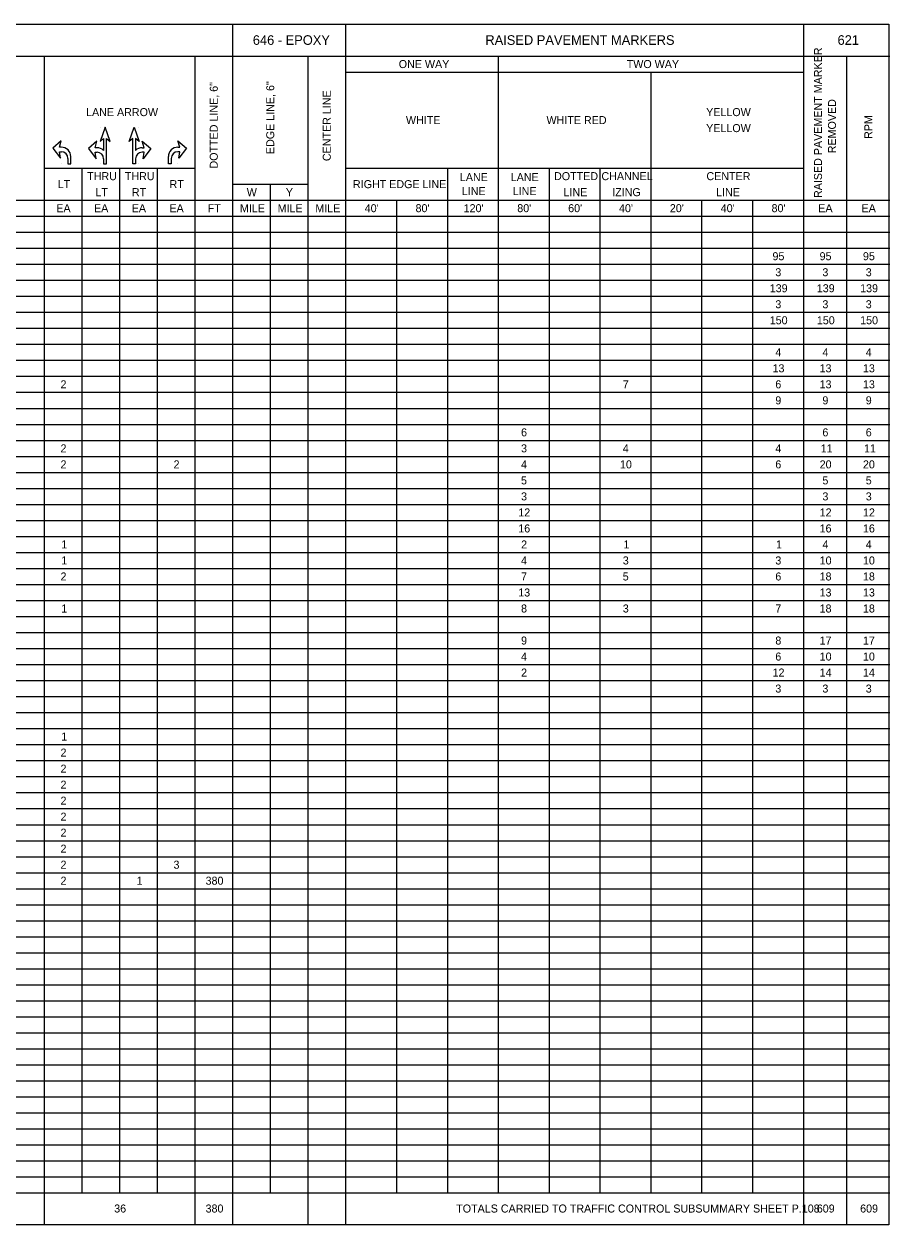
# Model space of a CAD drawing. Extents: x 12522 to 13018, y 1124 to 1902.
# Drawn here: x 12888.52 to 12903.67, y 1804.65 to 1825.65 of the extents above; entities that cross this region are included whole.
import ezdxf

# ---------------------------------------------------------------- set-up
doc = ezdxf.new("R2010")
doc.units = 0
for name, color, linetype in [('MT_X_Cells', 7, 'Continuous'), ('PM_P_Cells', 7, 'Continuous'), ('SC_Scratch1', 7, 'Continuous'), ('SH_Data', 7, 'Continuous'), ('SH_Text', 7, 'Continuous')]:
    doc.layers.add(name, color=color, linetype=linetype)

msp = doc.modelspace()

# ---------------------------------------------------------------- linework, layer by layer
at = {"layer": 'MT_X_Cells'}
for p, q in [((12889.941, 1823.846), (12889.854, 1823.596)), ((12889.854, 1823.596), (12889.916, 1823.646)), ((12889.858, 1823.846), (12889.858, 1823.846)), ((12890.028, 1823.596), (12889.941, 1823.846)), ((12889.966, 1823.208), (12889.966, 1823.646)), ((12889.966, 1823.646), (12890.028, 1823.596)), ((12890.362, 1823.596), (12890.449, 1823.846)), ((12890.424, 1823.646), (12890.362, 1823.596)), ((12890.424, 1823.208), (12890.424, 1823.646)), ((12890.449, 1823.846), (12890.535, 1823.596)), ((12890.535, 1823.596), (12890.474, 1823.646)), ((12890.532, 1823.846), (12890.532, 1823.846)), ((12889.799, 1823.599), (12889.649, 1823.471)), ((12889.649, 1823.471), (12889.783, 1823.295)), ((12889.766, 1823.487), (12889.799, 1823.599)), ((12889.799, 1823.487), (12889.766, 1823.487)), ((12890.624, 1823.487), (12890.59, 1823.599)), ((12890.59, 1823.599), (12890.74, 1823.471)), ((12890.59, 1823.487), (12890.624, 1823.487)), ((12890.74, 1823.471), (12890.607, 1823.295)), ((12889.783, 1823.295), (12889.766, 1823.407)), ((12889.766, 1823.407), (12889.801, 1823.407)), ((12889.916, 1823.292), (12889.916, 1823.208)), ((12890.474, 1823.292), (12890.474, 1823.208)), ((12890.624, 1823.407), (12890.588, 1823.407)), ((12890.607, 1823.295), (12890.624, 1823.407)), ((12889.858, 1823.208), (12889.858, 1823.208)), ((12889.916, 1823.208), (12889.966, 1823.208)), ((12890.474, 1823.208), (12890.424, 1823.208)), ((12890.532, 1823.208), (12890.532, 1823.208))]:
    msp.add_line(p, q, dxfattribs=at)
for points in [[(12889.916, 1823.646), (12889.916, 1823.44)], [(12890.474, 1823.646), (12890.474, 1823.44)]]:
    msp.add_lwpolyline(points, dxfattribs=at)
for centre, radius, start, end in [((12889.802, 1823.323), 0.164, 45.9534, 90.9085), ((12890.588, 1823.323), 0.164, 89.0915, 134.0466), ((12889.801, 1823.292), 0.115, 360, 90), ((12890.588, 1823.292), 0.115, 90, 180)]:
    msp.add_arc(centre, radius, start, end, dxfattribs=at)
at = {"layer": 'PM_P_Cells'}
for p, q in [((12889.175, 1823.608), (12889.025, 1823.48)), ((12889.025, 1823.48), (12889.159, 1823.304)), ((12889.142, 1823.496), (12889.175, 1823.608)), ((12889.175, 1823.496), (12889.142, 1823.496)), ((12889.175, 1823.608), (12889.175, 1823.608)), ((12891.214, 1823.608), (12891.214, 1823.608)), ((12891.248, 1823.496), (12891.214, 1823.608)), ((12891.214, 1823.608), (12891.364, 1823.48)), ((12891.214, 1823.496), (12891.248, 1823.496)), ((12891.364, 1823.48), (12891.231, 1823.304)), ((12889.159, 1823.304), (12889.142, 1823.416)), ((12889.142, 1823.416), (12889.177, 1823.416)), ((12889.292, 1823.301), (12889.292, 1823.208)), ((12889.342, 1823.208), (12889.342, 1823.332)), ((12891.048, 1823.208), (12891.048, 1823.332)), ((12891.098, 1823.301), (12891.098, 1823.208)), ((12891.248, 1823.416), (12891.213, 1823.416)), ((12891.231, 1823.304), (12891.248, 1823.416)), ((12889.175, 1823.208), (12889.175, 1823.208)), ((12889.292, 1823.208), (12889.342, 1823.208)), ((12891.098, 1823.208), (12891.048, 1823.208)), ((12891.214, 1823.208), (12891.214, 1823.208))]:
    msp.add_line(p, q, dxfattribs=at)
for centre, radius, start, end in [((12889.178, 1823.332), 0.164, 0, 90.9085), ((12891.212, 1823.332), 0.164, 89.0915, 180), ((12889.177, 1823.301), 0.115, 0, 90), ((12891.213, 1823.301), 0.115, 90, 180)]:
    msp.add_arc(centre, radius, start, end, dxfattribs=at)
at = {"layer": 'SC_Scratch1'}
msp.add_lwpolyline([(12873.148, 1825.65), (12903.648, 1825.65), (12903.648, 1804.65), (12873.148, 1804.65)], close=True, dxfattribs=at)
at = {"layer": 'SH_Data'}
for p, q in [((12892.171, 1825.65), (12892.171, 1804.667)), ((12894.148, 1825.65), (12894.148, 1804.667)), ((12902.153, 1825.65), (12902.153, 1804.667)), ((12873.148, 1825.09), (12903.668, 1825.09)), ((12888.877, 1825.09), (12888.877, 1804.667)), ((12891.513, 1825.09), (12891.513, 1804.667)), ((12893.489, 1825.09), (12893.489, 1804.667)), ((12896.816, 1825.09), (12896.816, 1805.21)), ((12902.91, 1825.09), (12902.91, 1804.667)), ((12894.148, 1824.81), (12902.153, 1824.81)), ((12899.484, 1824.81), (12899.484, 1805.21)), ((12888.877, 1823.13), (12891.513, 1823.13)), ((12889.536, 1823.13), (12889.536, 1805.21)), ((12890.195, 1823.13), (12890.195, 1805.21)), ((12890.854, 1823.13), (12890.854, 1805.21)), ((12894.148, 1823.13), (12902.153, 1823.13)), ((12895.927, 1823.13), (12895.927, 1805.21)), ((12897.705, 1823.13), (12897.705, 1805.21)), ((12898.595, 1823.13), (12898.595, 1805.21)), ((12892.171, 1822.85), (12893.489, 1822.85)), ((12892.83, 1822.85), (12892.83, 1805.21)), ((12880.477, 1822.57), (12903.668, 1822.57)), ((12895.037, 1822.57), (12895.037, 1805.21)), ((12900.374, 1822.57), (12900.374, 1805.21)), ((12901.263, 1822.57), (12901.263, 1805.21)), ((12873.148, 1822.29), (12903.668, 1822.29)), ((12873.148, 1822.01), (12903.668, 1822.01)), ((12873.148, 1821.73), (12903.668, 1821.73)), ((12873.148, 1821.45), (12903.668, 1821.45)), ((12873.148, 1821.17), (12903.668, 1821.17)), ((12873.148, 1820.89), (12903.668, 1820.89)), ((12873.148, 1820.61), (12903.668, 1820.61)), ((12873.148, 1820.33), (12903.668, 1820.33)), ((12873.148, 1820.05), (12903.668, 1820.05)), ((12873.148, 1819.77), (12903.668, 1819.77)), ((12873.148, 1819.49), (12903.668, 1819.49)), ((12873.148, 1819.21), (12903.668, 1819.21)), ((12873.148, 1818.93), (12903.668, 1818.93)), ((12873.148, 1818.65), (12903.668, 1818.65)), ((12873.148, 1818.37), (12903.668, 1818.37)), ((12873.148, 1818.09), (12903.668, 1818.09)), ((12873.148, 1817.81), (12903.668, 1817.81)), ((12873.148, 1817.53), (12903.668, 1817.53)), ((12873.148, 1817.25), (12903.668, 1817.25)), ((12873.148, 1816.97), (12903.668, 1816.97)), ((12873.148, 1816.69), (12903.668, 1816.69)), ((12873.148, 1816.41), (12903.668, 1816.41)), ((12873.148, 1816.13), (12903.668, 1816.13)), ((12873.148, 1815.85), (12903.668, 1815.85)), ((12873.148, 1815.57), (12903.668, 1815.57)), ((12873.148, 1815.29), (12903.668, 1815.29)), ((12873.148, 1815.01), (12903.668, 1815.01)), ((12873.148, 1814.73), (12903.668, 1814.73)), ((12873.148, 1814.45), (12903.668, 1814.45)), ((12873.148, 1814.17), (12903.668, 1814.17)), ((12873.148, 1813.89), (12903.668, 1813.89)), ((12873.148, 1813.61), (12903.668, 1813.61)), ((12873.148, 1813.33), (12903.668, 1813.33)), ((12873.148, 1813.05), (12903.668, 1813.05)), ((12873.148, 1812.77), (12903.668, 1812.77)), ((12873.148, 1812.49), (12903.668, 1812.49)), ((12873.148, 1812.21), (12903.668, 1812.21)), ((12873.148, 1811.93), (12903.668, 1811.93)), ((12873.148, 1811.65), (12903.668, 1811.65)), ((12873.148, 1811.37), (12903.668, 1811.37)), ((12873.148, 1811.09), (12903.668, 1811.09)), ((12873.148, 1810.81), (12903.668, 1810.81)), ((12873.148, 1810.53), (12903.668, 1810.53)), ((12873.148, 1810.25), (12903.668, 1810.25)), ((12873.148, 1809.97), (12903.668, 1809.97)), ((12873.148, 1809.69), (12903.668, 1809.69)), ((12873.148, 1809.41), (12903.668, 1809.41)), ((12873.148, 1809.13), (12903.668, 1809.13)), ((12873.148, 1808.85), (12903.668, 1808.85)), ((12873.148, 1808.57), (12903.668, 1808.57)), ((12873.148, 1808.29), (12903.668, 1808.29)), ((12873.148, 1808.01), (12903.668, 1808.01)), ((12873.148, 1807.73), (12903.668, 1807.73)), ((12873.148, 1807.45), (12903.668, 1807.45)), ((12873.148, 1807.17), (12903.668, 1807.17)), ((12873.148, 1806.89), (12903.668, 1806.89)), ((12873.148, 1806.61), (12903.668, 1806.61)), ((12873.148, 1806.33), (12903.668, 1806.33)), ((12873.148, 1806.05), (12903.668, 1806.05)), ((12873.148, 1805.77), (12903.668, 1805.77)), ((12873.148, 1805.49), (12903.668, 1805.49)), ((12873.148, 1805.21), (12903.668, 1805.21))]:
    msp.add_line(p, q, dxfattribs=at)

# ---------------------------------------------------------------- texts
at = {"layer": 'SH_Text'}
for s, height, p in [('646 - EPOXY', 0.168, (12892.525, 1825.286)), ('RAISED PAVEMENT MARKERS', 0.168, (12896.592, 1825.286)), ('621', 0.168, (12902.751, 1825.286)), ('ONE WAY', 0.14, (12895.077, 1824.88)), ('TWO WAY', 0.14, (12899.064, 1824.88)), ('LANE ARROW', 0.14, (12889.609, 1824.04)), ('YELLOW', 0.14, (12900.453, 1824.04)), ('WHITE', 0.14, (12895.203, 1823.9)), ('WHITE RED', 0.14, (12897.661, 1823.9)), ('YELLOW', 0.14, (12900.453, 1823.76)), ('THRU', 0.14, (12889.628, 1822.92)), ('THRU', 0.14, (12890.287, 1822.92)), ('LANE  ', 0.14, (12896.146, 1822.903)), ('LANE  ', 0.14, (12897.036, 1822.903)), ('DOTTED', 0.14, (12897.793, 1822.92)), ('CHANNEL', 0.14, (12898.622, 1822.92)), ('CENTER', 0.14, (12900.458, 1822.92)), ('LT', 0.14, (12889.112, 1822.78)), ('RT', 0.14, (12891.069, 1822.78)), ('RIGHT EDGE LINE', 0.14, (12894.276, 1822.78)), ('LT', 0.14, (12889.771, 1822.64)), ('RT', 0.14, (12890.41, 1822.64)), ('W', 0.14, (12892.419, 1822.64)), ('Y', 0.14, (12893.102, 1822.64)), ('LINE', 0.14, (12896.18, 1822.658)), ('LINE', 0.14, (12897.07, 1822.658)), ('LINE', 0.14, (12897.959, 1822.64)), ('IZING', 0.14, (12898.81, 1822.64)), ('LINE', 0.14, (12900.627, 1822.64)), ('EA', 0.14, (12889.089, 1822.36)), ('EA', 0.14, (12889.748, 1822.36)), ('EA', 0.14, (12890.407, 1822.36)), ('EA', 0.14, (12891.066, 1822.36)), ('FT', 0.14, (12891.736, 1822.36)), ('MILE', 0.14, (12892.3, 1822.36)), ('MILE', 0.14, (12892.959, 1822.36)), ('MILE', 0.14, (12893.618, 1822.36)), ("40'", 0.14, (12894.482, 1822.36)), ("80'", 0.14, (12895.371, 1822.36)), ("120'", 0.14, (12896.212, 1822.36)), ("80'", 0.14, (12897.15, 1822.36)), ("60'", 0.14, (12898.04, 1822.36)), ("40'", 0.14, (12898.929, 1822.36)), ("20'", 0.14, (12899.818, 1822.36)), ("40'", 0.14, (12900.708, 1822.36)), ("80'", 0.14, (12901.597, 1822.36)), ('EA', 0.14, (12902.414, 1822.36)), ('EA', 0.14, (12903.171, 1822.36)), ('95', 0.14, (12901.613, 1821.52)), ('95', 0.14, (12902.437, 1821.52)), ('95', 0.14, (12903.195, 1821.52)), ('3', 0.14, (12901.663, 1821.24)), ('3', 0.14, (12902.486, 1821.24)), ('3', 0.14, (12903.244, 1821.24)), ('139', 0.14, (12901.565, 1820.96)), ('139', 0.14, (12902.388, 1820.96)), ('139', 0.14, (12903.146, 1820.96)), ('3', 0.14, (12901.663, 1820.68)), ('3', 0.14, (12902.486, 1820.68)), ('3', 0.14, (12903.244, 1820.68)), ('150', 0.14, (12901.565, 1820.4)), ('150', 0.14, (12902.389, 1820.4)), ('150', 0.14, (12903.146, 1820.4)), ('4', 0.14, (12901.663, 1819.84)), ('4', 0.14, (12902.487, 1819.84)), ('4', 0.14, (12903.244, 1819.84)), ('13', 0.14, (12901.614, 1819.56)), ('13', 0.14, (12902.437, 1819.56)), ('13', 0.14, (12903.195, 1819.56)), ('2', 0.14, (12889.162, 1819.28)), ('7', 0.14, (12898.995, 1819.28)), ('6', 0.14, (12901.663, 1819.28)), ('13', 0.14, (12902.437, 1819.28)), ('13', 0.14, (12903.195, 1819.28)), ('9', 0.14, (12901.663, 1819)), ('9', 0.14, (12902.486, 1819)), ('9', 0.14, (12903.244, 1819)), ('6', 0.14, (12897.216, 1818.44)), ('6', 0.14, (12902.486, 1818.44)), ('6', 0.14, (12903.244, 1818.44)), ('2', 0.14, (12889.162, 1818.16)), ('3', 0.14, (12897.216, 1818.16)), ('4', 0.14, (12898.995, 1818.16)), ('4', 0.14, (12901.663, 1818.16)), ('11', 0.14, (12902.456, 1818.16)), ('11', 0.14, (12903.214, 1818.16)), ('2', 0.14, (12889.162, 1817.88)), ('2', 0.14, (12891.139, 1817.88)), ('4', 0.14, (12897.216, 1817.88)), ('10', 0.14, (12898.946, 1817.88)), ('6', 0.14, (12901.663, 1817.88)), ('20', 0.14, (12902.438, 1817.88)), ('20', 0.14, (12903.195, 1817.88)), ('5', 0.14, (12897.215, 1817.6)), ('5', 0.14, (12902.486, 1817.6)), ('5', 0.14, (12903.244, 1817.6)), ('3', 0.14, (12897.216, 1817.32)), ('3', 0.14, (12902.486, 1817.32)), ('3', 0.14, (12903.244, 1817.32)), ('12', 0.14, (12897.168, 1817.04)), ('12', 0.14, (12902.438, 1817.04)), ('12', 0.14, (12903.196, 1817.04)), ('16', 0.14, (12897.167, 1816.76)), ('16', 0.14, (12902.437, 1816.76)), ('16', 0.14, (12903.195, 1816.76)), ('1', 0.14, (12889.174, 1816.48)), ('2', 0.14, (12897.217, 1816.48)), ('1', 0.14, (12899.007, 1816.48)), ('1', 0.14, (12901.675, 1816.48)), ('4', 0.14, (12902.487, 1816.48)), ('4', 0.14, (12903.244, 1816.48)), ('1', 0.14, (12889.174, 1816.2)), ('4', 0.14, (12897.216, 1816.2)), ('3', 0.14, (12898.995, 1816.2)), ('3', 0.14, (12901.663, 1816.2)), ('10', 0.14, (12902.438, 1816.2)), ('10', 0.14, (12903.195, 1816.2)), ('2', 0.14, (12889.162, 1815.92)), ('7', 0.14, (12897.216, 1815.92)), ('5', 0.14, (12898.994, 1815.92)), ('6', 0.14, (12901.663, 1815.92)), ('18', 0.14, (12902.437, 1815.92)), ('18', 0.14, (12903.195, 1815.92)), ('13', 0.14, (12897.167, 1815.64)), ('13', 0.14, (12902.437, 1815.64)), ('13', 0.14, (12903.195, 1815.64)), ('1', 0.14, (12889.174, 1815.36)), ('8', 0.14, (12897.216, 1815.36)), ('3', 0.14, (12898.995, 1815.36)), ('7', 0.14, (12901.663, 1815.36)), ('18', 0.14, (12902.437, 1815.36)), ('18', 0.14, (12903.195, 1815.36)), ('9', 0.14, (12897.216, 1814.8)), ('8', 0.14, (12901.663, 1814.8)), ('17', 0.14, (12902.437, 1814.8)), ('17', 0.14, (12903.195, 1814.8)), ('4', 0.14, (12897.216, 1814.52)), ('6', 0.14, (12901.663, 1814.52)), ('10', 0.14, (12902.438, 1814.52)), ('10', 0.14, (12903.195, 1814.52)), ('2', 0.14, (12897.217, 1814.24)), ('12', 0.14, (12901.615, 1814.24)), ('14', 0.14, (12902.438, 1814.24)), ('14', 0.14, (12903.195, 1814.24)), ('3', 0.14, (12901.663, 1813.96)), ('3', 0.14, (12902.486, 1813.96)), ('3', 0.14, (12903.244, 1813.96)), ('1', 0.14, (12889.174, 1813.12)), ('2', 0.14, (12889.162, 1812.84)), ('2', 0.14, (12889.162, 1812.56)), ('2', 0.14, (12889.162, 1812.28)), ('2', 0.14, (12889.162, 1812)), ('2', 0.14, (12889.162, 1811.72)), ('2', 0.14, (12889.162, 1811.44)), ('2', 0.14, (12889.162, 1811.16)), ('2', 0.14, (12889.162, 1810.88)), ('3', 0.14, (12891.138, 1810.88)), ('2', 0.14, (12889.162, 1810.6)), ('1', 0.14, (12890.492, 1810.6)), ('380', 0.14, (12891.699, 1810.6)), ('36', 0.14, (12890.101, 1804.868)), ('380', 0.14, (12891.699, 1804.868)), ('TOTALS CARRIED TO TRAFFIC CONTROL SUBSUMMARY SHEET P.108', 0.14, (12896.082, 1804.868)), ('609', 0.14, (12902.388, 1804.868)), ('609', 0.14, (12903.146, 1804.868))]:
    msp.add_text(s, height=height, dxfattribs=at).set_placement(p)
for s, p in [('RAISED PAVEMENT MARKER ', (12902.479, 1822.608)), ('DOTTED LINE, 6"', (12891.912, 1823.123)), ('EDGE LINE, 6"', (12892.9, 1823.376)), ('CENTER LINE', (12893.888, 1823.253)), ('REMOVED', (12902.724, 1823.39)), ('RPM', (12903.359, 1823.641))]:
    msp.add_text(s, height=0.14, rotation=90, dxfattribs=at).set_placement(p)

doc.saveas('drawing.dxf')
